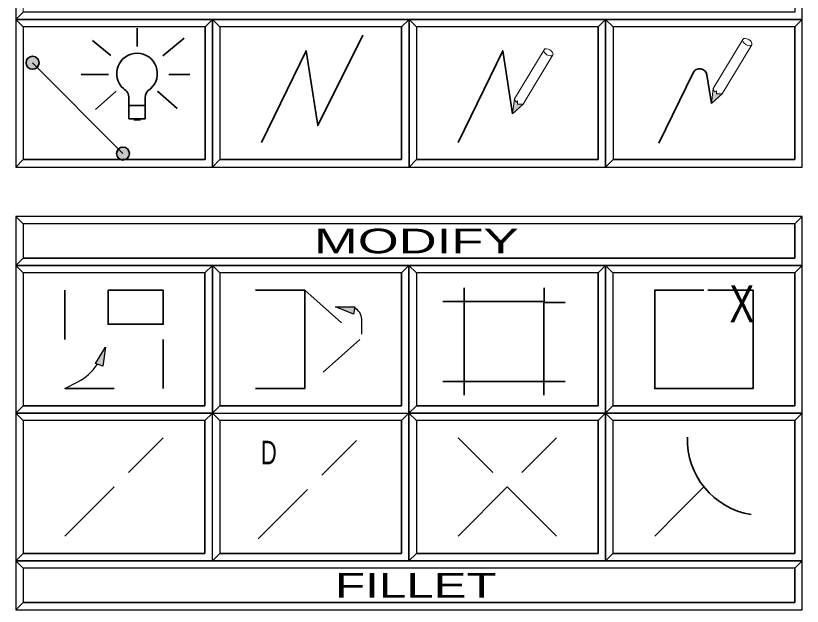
# Model space of a CAD drawing. Extents: x 95906.9 to 95918.9, y 90964.8 to 90972.9.
# Drawn here: x 95908.935 to 95910.535, y 90966.096 to 90967.296 of the extents above; entities that cross this region are included whole.
import ezdxf
from ezdxf.enums import TextEntityAlignment as Align

# ---------------------------------------------------------------- set-up
doc = ezdxf.new("R2010")
doc.units = 0
doc.header["$LTSCALE"] = 0.019
doc.linetypes.add('MEDIUM_DASHED', pattern=[4.5, 3, -1.5])
for name, color, linetype, lineweight in [('1', 7, 'Continuous', 25), ('11', 7, 'Continuous', 25), ('12', 7, 'Continuous', 25), ('18', 7, 'Continuous', 25), ('2', 7, 'Continuous', 13), ('3', 7, 'Continuous', 25), ('4', 7, 'Continuous', 35), ('6', 7, 'Continuous', 35), ('7', 7, 'Continuous', 35)]:
    doc.layers.add(name, color=color, linetype=linetype, lineweight=lineweight)

msp = doc.modelspace()

# ---------------------------------------------------------------- hatches: boundary and pattern name
at = {"layer": '6'}
for points in [[(95908.9819, 90967.2006, 1), (95908.9555, 90967.2006, 1)], [(95910.3535, 90967.1484), (95910.3497, 90967.1176), (95910.3715, 90967.1376), (95910.3601, 90967.1372), (95910.3601, 90967.1438), (95910.3562, 90967.1412)], [(95909.9489, 90967.1275), (95909.9451, 90967.0967), (95909.9669, 90967.1167), (95909.9555, 90967.1163), (95909.9555, 90967.1229), (95909.9516, 90967.1203)], [(95909.1659, 90967.016, 1), (95909.1395, 90967.016, 1)], [(95909.5847, 90966.7042), (95909.6243, 90966.7047), (95909.6217, 90966.6895)], [(95909.1174, 90966.6228), (95909.1115, 90966.5841), (95909.097, 90966.5893)]]:
    msp.add_hatch(color=256, dxfattribs=at).paths.add_polyline_path(points)

# ---------------------------------------------------------------- linework, layer by layer
at = {"layer": '1'}
for points in [[(95908.9346, 90967.2887), (95910.5346, 90967.2887), (95910.5346, 90967.3887), (95908.9346, 90967.3887)], [(95908.9346, 90966.9887), (95909.3346, 90966.9887), (95909.3346, 90967.2887), (95908.9346, 90967.2887)], [(95909.3346, 90966.9887), (95909.7346, 90966.9887), (95909.7346, 90967.2887), (95909.3346, 90967.2887)], [(95909.7346, 90966.9887), (95910.1346, 90966.9887), (95910.1346, 90967.2887), (95909.7346, 90967.2887)], [(95910.1346, 90966.9887), (95910.5346, 90966.9887), (95910.5346, 90967.2887), (95910.1346, 90967.2887)], [(95908.9345, 90966.7883), (95910.5345, 90966.7883), (95910.5345, 90966.8883), (95908.9345, 90966.8883)], [(95908.9345, 90966.4883), (95909.3345, 90966.4883), (95909.3345, 90966.7883), (95908.9345, 90966.7883)], [(95909.3345, 90966.4883), (95909.7345, 90966.4883), (95909.7345, 90966.7883), (95909.3345, 90966.7883)], [(95909.7345, 90966.4883), (95910.1345, 90966.4883), (95910.1345, 90966.7883), (95909.7345, 90966.7883)], [(95910.1345, 90966.4883), (95910.5345, 90966.4883), (95910.5345, 90966.7883), (95910.1345, 90966.7883)], [(95908.9345, 90966.1883), (95909.3345, 90966.1883), (95909.3345, 90966.4883), (95908.9345, 90966.4883)], [(95909.7345, 90966.1883), (95910.1345, 90966.1883), (95910.1345, 90966.4883), (95909.7345, 90966.4883)], [(95910.1345, 90966.1883), (95910.5345, 90966.1883), (95910.5345, 90966.4883), (95910.1345, 90966.4883)], [(95908.9345, 90966.0883), (95910.5345, 90966.0883), (95910.5345, 90966.1883), (95908.9345, 90966.1883)]]:
    msp.add_lwpolyline(points, close=True, dxfattribs=at)
at = {"layer": '11'}
for points in [[(95908.9496, 90967.0037), (95909.3196, 90967.0037), (95909.3196, 90967.2737), (95908.9496, 90967.2737)], [(95909.3496, 90967.0037), (95909.7196, 90967.0037), (95909.7196, 90967.2737), (95909.3496, 90967.2737)], [(95909.7496, 90967.0037), (95910.1196, 90967.0037), (95910.1196, 90967.2737), (95909.7496, 90967.2737)], [(95910.1496, 90967.0037), (95910.5196, 90967.0037), (95910.5196, 90967.2737), (95910.1496, 90967.2737)], [(95908.9495, 90966.5033), (95909.3195, 90966.5033), (95909.3195, 90966.7733), (95908.9495, 90966.7733)], [(95909.3495, 90966.5033), (95909.7195, 90966.5033), (95909.7195, 90966.7733), (95909.3495, 90966.7733)], [(95909.7495, 90966.5033), (95910.1195, 90966.5033), (95910.1195, 90966.7733), (95909.7495, 90966.7733)], [(95910.1495, 90966.5033), (95910.5195, 90966.5033), (95910.5195, 90966.7733), (95910.1495, 90966.7733)], [(95908.9495, 90966.2033), (95909.3195, 90966.2033), (95909.3195, 90966.4733), (95908.9495, 90966.4733)], [(95909.3495, 90966.2033), (95909.7195, 90966.2033), (95909.7195, 90966.4733), (95909.3495, 90966.4733)], [(95909.7495, 90966.2033), (95910.1195, 90966.2033), (95910.1195, 90966.4733), (95909.7495, 90966.4733)], [(95910.1495, 90966.2033), (95910.5195, 90966.2033), (95910.5195, 90966.4733), (95910.1495, 90966.4733)]]:
    msp.add_lwpolyline(points, close=True, dxfattribs=at)
at = {"layer": '12'}
for points in [[(95908.9496, 90967.0037), (95909.3196, 90967.0037), (95909.3196, 90967.2737), (95908.9496, 90967.2737)], [(95908.9495, 90966.5033), (95909.3195, 90966.5033), (95909.3195, 90966.7733), (95908.9495, 90966.7733)], [(95908.9495, 90966.2033), (95909.3195, 90966.2033), (95909.3195, 90966.4733), (95908.9495, 90966.4733)]]:
    msp.add_lwpolyline(points, close=True, dxfattribs=at)
at = {"layer": '18'}
for points in [[(95908.9495, 90966.8033), (95910.5195, 90966.8033), (95910.5195, 90966.8733), (95908.9495, 90966.8733)], [(95908.9495, 90966.1033), (95910.5195, 90966.1033), (95910.5195, 90966.1733), (95908.9495, 90966.1733)]]:
    msp.add_lwpolyline(points, close=True, dxfattribs=at)
at = {"layer": '2'}
for points in [[(95908.9346, 90967.3887), (95908.9346, 90967.2887), (95908.9496, 90967.3037), (95908.9496, 90967.3737), (95910.5196, 90967.3737), (95910.5346, 90967.3887)], [(95908.9346, 90967.2887), (95908.9346, 90966.9887), (95908.9496, 90967.0037), (95908.9496, 90967.2737), (95909.3196, 90967.2737), (95909.3346, 90967.2887)], [(95909.3346, 90967.2887), (95909.3346, 90966.9887), (95909.3496, 90967.0037), (95909.3496, 90967.2737), (95909.7196, 90967.2737), (95909.7346, 90967.2887)], [(95909.7346, 90967.2887), (95909.7346, 90966.9887), (95909.7496, 90967.0037), (95909.7496, 90967.2737), (95910.1196, 90967.2737), (95910.1346, 90967.2887)], [(95910.1346, 90967.2887), (95910.1346, 90966.9887), (95910.1496, 90967.0037), (95910.1496, 90967.2737), (95910.5196, 90967.2737), (95910.5346, 90967.2887)], [(95908.9345, 90966.8883), (95908.9345, 90966.7883), (95908.9495, 90966.8033), (95908.9495, 90966.8733), (95910.5195, 90966.8733), (95910.5345, 90966.8883)], [(95908.9345, 90966.7883), (95908.9345, 90966.4883), (95908.9495, 90966.5033), (95908.9495, 90966.7733), (95909.3195, 90966.7733), (95909.3345, 90966.7883)], [(95909.3345, 90966.7883), (95909.3345, 90966.4883), (95909.3495, 90966.5033), (95909.3495, 90966.7733), (95909.7195, 90966.7733), (95909.7345, 90966.7883)], [(95909.7345, 90966.7883), (95909.7345, 90966.4883), (95909.7495, 90966.5033), (95909.7495, 90966.7733), (95910.1195, 90966.7733), (95910.1345, 90966.7883)], [(95910.1345, 90966.7883), (95910.1345, 90966.4883), (95910.1495, 90966.5033), (95910.1495, 90966.7733), (95910.5195, 90966.7733), (95910.5345, 90966.7883)], [(95908.9345, 90966.4883), (95908.9345, 90966.1883), (95908.9495, 90966.2033), (95908.9495, 90966.4733), (95909.3195, 90966.4733), (95909.3345, 90966.4883)], [(95909.3345, 90966.4883), (95909.3345, 90966.1883), (95909.3495, 90966.2033), (95909.3495, 90966.4733), (95909.7195, 90966.4733), (95909.7345, 90966.4883)], [(95909.7345, 90966.4883), (95909.7345, 90966.1883), (95909.7495, 90966.2033), (95909.7495, 90966.4733), (95910.1195, 90966.4733), (95910.1345, 90966.4883)], [(95910.1345, 90966.4883), (95910.1345, 90966.1883), (95910.1495, 90966.2033), (95910.1495, 90966.4733), (95910.5195, 90966.4733), (95910.5345, 90966.4883)], [(95908.9345, 90966.1883), (95908.9345, 90966.0883), (95908.9495, 90966.1033), (95908.9495, 90966.1733), (95910.5195, 90966.1733), (95910.5345, 90966.1883)]]:
    msp.add_lwpolyline(points, close=True, dxfattribs=at)
at = {"layer": '3'}
for points in [[(95908.9346, 90967.2887), (95910.5346, 90967.2887), (95910.5346, 90967.3887), (95910.5196, 90967.3737), (95910.5196, 90967.3037), (95908.9496, 90967.3037)], [(95908.9346, 90966.9887), (95909.3346, 90966.9887), (95909.3346, 90967.2887), (95909.3196, 90967.2737), (95909.3196, 90967.0037), (95908.9496, 90967.0037)], [(95909.3346, 90966.9887), (95909.7346, 90966.9887), (95909.7346, 90967.2887), (95909.7196, 90967.2737), (95909.7196, 90967.0037), (95909.3496, 90967.0037)], [(95909.7346, 90966.9887), (95910.1346, 90966.9887), (95910.1346, 90967.2887), (95910.1196, 90967.2737), (95910.1196, 90967.0037), (95909.7496, 90967.0037)], [(95910.1346, 90966.9887), (95910.5346, 90966.9887), (95910.5346, 90967.2887), (95910.5196, 90967.2737), (95910.5196, 90967.0037), (95910.1496, 90967.0037)], [(95908.9345, 90966.7883), (95910.5345, 90966.7883), (95910.5345, 90966.8883), (95910.5195, 90966.8733), (95910.5195, 90966.8033), (95908.9495, 90966.8033)], [(95908.9345, 90966.4883), (95909.3345, 90966.4883), (95909.3345, 90966.7883), (95909.3195, 90966.7733), (95909.3195, 90966.5033), (95908.9495, 90966.5033)], [(95909.3345, 90966.4883), (95909.7345, 90966.4883), (95909.7345, 90966.7883), (95909.7195, 90966.7733), (95909.7195, 90966.5033), (95909.3495, 90966.5033)], [(95909.7345, 90966.4883), (95910.1345, 90966.4883), (95910.1345, 90966.7883), (95910.1195, 90966.7733), (95910.1195, 90966.5033), (95909.7495, 90966.5033)], [(95910.1345, 90966.4883), (95910.5345, 90966.4883), (95910.5345, 90966.7883), (95910.5195, 90966.7733), (95910.5195, 90966.5033), (95910.1495, 90966.5033)], [(95908.9345, 90966.1883), (95909.3345, 90966.1883), (95909.3345, 90966.4883), (95909.3195, 90966.4733), (95909.3195, 90966.2033), (95908.9495, 90966.2033)], [(95909.3345, 90966.1883), (95909.7345, 90966.1883), (95909.7345, 90966.4883), (95909.7195, 90966.4733), (95909.7195, 90966.2033), (95909.3495, 90966.2033)], [(95909.7345, 90966.1883), (95910.1345, 90966.1883), (95910.1345, 90966.4883), (95910.1195, 90966.4733), (95910.1195, 90966.2033), (95909.7495, 90966.2033)], [(95910.1345, 90966.1883), (95910.5345, 90966.1883), (95910.5345, 90966.4883), (95910.5195, 90966.4733), (95910.5195, 90966.2033), (95910.1495, 90966.2033)], [(95908.9345, 90966.0883), (95910.5345, 90966.0883), (95910.5345, 90966.1883), (95910.5195, 90966.1733), (95910.5195, 90966.1033), (95908.9495, 90966.1033)]]:
    msp.add_lwpolyline(points, close=True, dxfattribs=at)
at = {"layer": '4'}
for p, q in [((95908.9496, 90967.2737), (95908.9346, 90967.2887)), ((95909.3496, 90967.2737), (95909.3346, 90967.2887)), ((95909.7496, 90967.2737), (95909.7346, 90967.2887)), ((95910.1496, 90967.2737), (95910.1346, 90967.2887)), ((95908.9495, 90966.8733), (95908.9345, 90966.8883)), ((95908.9495, 90966.7733), (95908.9345, 90966.7883)), ((95909.3495, 90966.7733), (95909.3345, 90966.7883)), ((95909.7495, 90966.7733), (95909.7345, 90966.7883)), ((95910.1495, 90966.7733), (95910.1345, 90966.7883)), ((95908.9495, 90966.4733), (95908.9345, 90966.4883)), ((95909.3495, 90966.4733), (95909.3345, 90966.4883)), ((95909.7495, 90966.4733), (95909.7345, 90966.4883)), ((95910.1495, 90966.4733), (95910.1345, 90966.4883)), ((95908.9495, 90966.1733), (95908.9345, 90966.1883))]:
    msp.add_line(p, q, dxfattribs=at)
at = {"layer": '6'}
for p, q in [((95909.1813, 90967.2334), (95909.1813, 90967.2707)), ((95909.1281, 90967.2154), (95909.091, 90967.246)), ((95909.2335, 90967.2146), (95909.2774, 90967.2508)), ((95909.1527, 90967.016), (95908.9687, 90967.2006)), ((95909.1233, 90967.177), (95909.0679, 90967.177)), ((95909.2457, 90967.177), (95909.2884, 90967.177)), ((95910.2427, 90967.037), (95910.3124, 90967.1803)), ((95910.3407, 90967.176), (95910.3497, 90967.1176)), ((95909.139, 90967.1427), (95909.097, 90967.1054)), ((95909.2231, 90967.1431), (95909.2632, 90967.1076)), ((95909.1649, 90967.1286), (95909.1649, 90967.0868)), ((95909.1981, 90967.1295), (95909.1981, 90967.0868)), ((95909.1649, 90967.1135), (95909.1981, 90967.1135)), ((95909.1649, 90967.0868), (95909.1981, 90967.0868)), ((95909.175, 90967.0849), (95909.1881, 90967.0849)), ((95909.0345, 90966.2383), (95909.1345, 90966.3383)), ((95909.4278, 90966.2329), (95909.5278, 90966.3329)), ((95909.8345, 90966.2383), (95909.9345, 90966.3383)), ((95910.0345, 90966.2383), (95909.9345, 90966.3383)), ((95910.2345, 90966.2383), (95910.2845, 90966.2883))]:
    msp.add_line(p, q, dxfattribs=at)
at = {"layer": '6', "lineweight": 13}
for p, q in [((95910.3535, 90967.1484), (95910.4138, 90967.2481)), ((95910.3715, 90967.1376), (95910.4318, 90967.2373)), ((95909.9489, 90967.1275), (95910.0092, 90967.2272)), ((95909.9669, 90967.1167), (95910.0272, 90967.2164))]:
    msp.add_line(p, q, dxfattribs=at)
at = {"layer": '6', "linetype": 'MEDIUM_DASHED'}
for p, q in [((95909.8466, 90966.715), (95909.8466, 90966.7434)), ((95910.0094, 90966.715), (95910.0094, 90966.7434)), ((95909.8032, 90966.715), (95909.8466, 90966.715)), ((95910.0086, 90966.7133), (95910.052, 90966.7133)), ((95909.8032, 90966.553), (95909.8466, 90966.553)), ((95909.8466, 90966.5246), (95909.8466, 90966.553)), ((95910.0086, 90966.553), (95910.052, 90966.553)), ((95910.0086, 90966.5246), (95910.0086, 90966.553)), ((95909.2345, 90966.4383), (95909.1345, 90966.3383)), ((95909.8345, 90966.4383), (95909.9345, 90966.3383)), ((95910.0345, 90966.4383), (95909.9345, 90966.3383)), ((95909.6278, 90966.4329), (95909.5278, 90966.3329)), ((95910.3345, 90966.3383), (95910.2845, 90966.2883))]:
    msp.add_line(p, q, dxfattribs=at)
at = {"layer": '6', "lineweight": 25}
for p, q in [((95909.6385, 90966.6489), (95909.6385, 90966.6792)), ((95909.0345, 90966.5383), (95909.0609, 90966.5518))]:
    msp.add_line(p, q, dxfattribs=at)
at = {"layer": '6'}
for points in [[(95909.4346, 90967.0387), (95909.5252, 90967.225), (95909.5488, 90967.0728), (95909.6406, 90967.2565)], [(95909.4346, 90967.0387), (95909.5252, 90967.225), (95909.5488, 90967.0728), (95909.6406, 90967.2565)], [(95909.8346, 90967.0387), (95909.9252, 90967.225), (95909.9451, 90967.0967)], [(95909.4222, 90966.7383), (95909.5223, 90966.7383), (95909.5223, 90966.5383), (95909.4224, 90966.5383)], [(95910.3346, 90966.7383), (95910.2345, 90966.7383), (95910.2345, 90966.5383), (95910.4345, 90966.5383), (95910.4345, 90966.6383)], [(95910.0094, 90966.715), (95909.8466, 90966.715), (95909.8466, 90966.553), (95910.0086, 90966.553), (95910.0086, 90966.7133)]]:
    msp.add_lwpolyline(points, dxfattribs=at)
at = {"layer": '6', "lineweight": 13}
for points in [[(95910.3535, 90967.1484), (95910.3497, 90967.1176), (95910.3715, 90967.1376), (95910.3601, 90967.1372), (95910.3601, 90967.1438), (95910.3562, 90967.1412)], [(95909.9489, 90967.1275), (95909.9451, 90967.0967), (95909.9669, 90967.1167), (95909.9555, 90967.1163), (95909.9555, 90967.1229), (95909.9516, 90967.1203)]]:
    msp.add_lwpolyline(points, close=True, dxfattribs=at)
at = {"layer": '6', "linetype": 'MEDIUM_DASHED'}
msp.add_lwpolyline([(95909.2345, 90966.7383), (95909.0345, 90966.7383), (95909.0345, 90966.5383), (95909.2345, 90966.5383)], close=True, dxfattribs=at)
at = {"layer": '6'}
msp.add_lwpolyline([(95909.2345, 90966.7383), (95909.1223, 90966.7383), (95909.1223, 90966.6691), (95909.2345, 90966.6691)], close=True, dxfattribs=at)
at = {"layer": '6', "linetype": 'MEDIUM_DASHED'}
for points in [[(95909.5223, 90966.7383), (95909.6345, 90966.6383), (95909.5223, 90966.5383)], [(95910.3427, 90966.7383), (95910.4345, 90966.7383), (95910.4345, 90966.6383)]]:
    msp.add_lwpolyline(points, dxfattribs=at)
at = {"layer": '6', "lineweight": 25}
for points in [[(95909.5847, 90966.7042), (95909.6243, 90966.7047), (95909.6217, 90966.6895)], [(95909.1174, 90966.6228), (95909.1115, 90966.5841), (95909.097, 90966.5893)]]:
    msp.add_lwpolyline(points, close=True, dxfattribs=at)
at = {"layer": '6'}
for centre in [(95908.9687, 90967.2006), (95909.1527, 90967.016)]:
    msp.add_circle(centre, 0.0132, dxfattribs=at)
for centre, radius, start, end in [((95909.1813, 90967.1787), 0.0413, 311.0003, 227.9341), ((95910.3258, 90967.1737), 0.015, 8.8599, 154.0466), ((95909.1429, 90967.1288), 0.022, 359.4769, 60.9125), ((95909.2182, 90967.13), 0.0201, 119.0875, 181.351), ((95910.4553, 90966.4345), 0.1544, 178.1343, 260.7711)]:
    msp.add_arc(centre, radius, start, end, dxfattribs=at)
at = {"layer": '6', "lineweight": 25}
for centre, radius, start, end in [((95909.6135, 90966.6792), 0.025, 0, 67.0459), ((95909.0153, 90966.6408), 0.1, 297.1547, 327.7877)]:
    msp.add_arc(centre, radius, start, end, dxfattribs=at)
at = {"layer": '6', "lineweight": 13}
for centre in [(95910.4228, 90967.2427), (95910.0182, 90967.2218)]:
    msp.add_ellipse(centre, major_axis=(-0.009, 0.0054), ratio=0.555562, dxfattribs=at)

# ---------------------------------------------------------------- texts
at = {"layer": '6'}
for s, height, width, p in [('X', 0.0752, 0.75, (95910.4117, 90966.6728)), ('D', 0.048, 0.7, (95909.4493, 90966.3842))]:
    msp.add_text(s, height=height, dxfattribs=dict(at, width=width)).set_placement(p, align=Align.CENTER)
at = {"layer": '7'}
for s, width, p in [('         MODIFY        ', 1.6, (95909.7344, 90966.8133)), ('         FILLET        ', 1.5, (95909.7345, 90966.1133))]:
    msp.add_text(s, height=0.04999, dxfattribs=dict(at, width=width)).set_placement(p, align=Align.CENTER)

doc.saveas('drawing.dxf')
